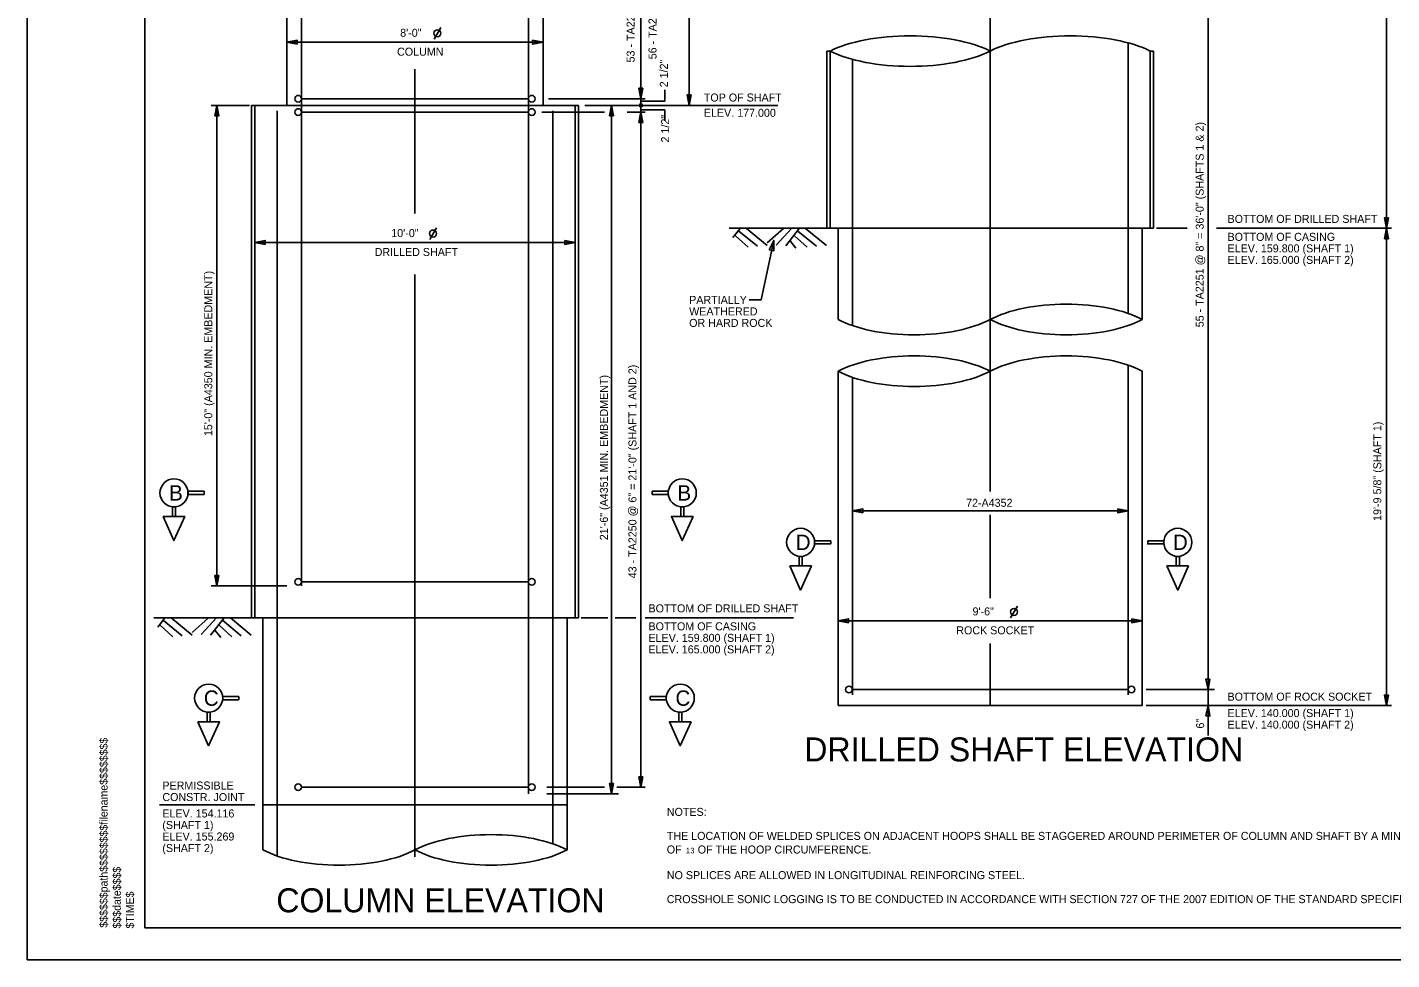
# Model space of a CAD drawing. Extents: x -225.1 to -152.9, y -16.8 to 27.2.
# Drawn here: x -225.08 to -182.47, y -16.78 to 12.34 of the extents above; entities that cross this region are included whole.
import ezdxf

# ---------------------------------------------------------------- set-up
doc = ezdxf.new("R2010")
doc.units = 0
for name, color, linetype in [('BR_AUTO DIMENSION', 7, 'Continuous'), ('BR_BORDER LINES', 7, 'Continuous'), ('BR_CENTER LINES', 7, 'Continuous'), ('BR_CONCRETE', 7, 'Continuous'), ('BR_GRID LINES', 7, 'Continuous'), ('BR_REBAR', 7, 'Continuous'), ('BR_STRUCTURAL STEEL', 7, 'Continuous'), ('BR_TEXT', 7, 'Continuous'), ('Level 31', 7, 'Continuous'), ('RD_SHT_ID', 7, 'Continuous')]:
    doc.layers.add(name, color=color, linetype=linetype)

msp = doc.modelspace()

# ---------------------------------------------------------------- linework, layer by layer
at = {"layer": 'BR_AUTO DIMENSION'}
for p, q in [((-204.41, 23.713), (-204.41, 9.901)), ((-205.915, 23.213), (-205.915, 10.109)), ((-182.63, 22.62), (-182.63, 6.062)), ((-188.204, 22.12), (-188.204, -8.337)), ((-216.97, 11.875), (-208.97, 11.875)), ((-205.169, 10.037), (-205.169, 10.382)), ((-218.137, 9.901), (-219.334, 9.901)), ((-219.156, 9.901), (-219.156, -5.099)), ((-208.796, 10.109), (-205.776, 10.109)), ((-207.661, 9.901), (-201.638, 9.901)), ((-206.836, 9.901), (-206.836, -11.599)), ((-205.915, 10.109), (-205.915, 9.692)), ((-205.169, 10.037), (-205.915, 10.037)), ((-209.012, 9.692), (-207.049, 9.692)), ((-206.342, 9.692), (-205.776, 9.692)), ((-205.169, 9.764), (-205.915, 9.764)), ((-205.915, 9.692), (-205.915, -11.391)), ((-205.169, 9.764), (-205.169, 9.419)), ((-189.813, 6.062), (-188.85, 6.062)), ((-187.938, 6.062), (-182.47, 6.062)), ((-182.63, 6.062), (-182.63, -8.837)), ((-217.97, 5.62), (-207.97, 5.62)), ((-202.163, 3.833), (-201.767, 5.683)), ((-202.537, 3.833), (-202.163, 3.833)), ((-199.311, -2.757), (-196.546, -2.757)), ((-196.546, -2.757), (-190.7, -2.757)), ((-216.972, -5.099), (-219.334, -5.099)), ((-207.777, -6.099), (-206.951, -6.099)), ((-206.72, -6.099), (-206.07, -6.099)), ((-205.786, -6.099), (-201.148, -6.099)), ((-199.756, -6.193), (-190.256, -6.193)), ((-190.138, -8.337), (-188.002, -8.337)), ((-188.204, -8.337), (-188.204, -9.772)), ((-190.138, -8.837), (-182.47, -8.837)), ((-208.847, -11.391), (-207.049, -11.391)), ((-206.665, -11.391), (-205.776, -11.391)), ((-208.847, -11.599), (-206.617, -11.599)), ((-220.947, -11.94), (-217.966, -11.94))]:
    msp.add_line(p, q, dxfattribs=at)
for points in [[(-216.645, 11.812), (-216.97, 11.875), (-216.645, 11.937)], [(-209.295, 11.937), (-208.97, 11.875), (-209.295, 11.812)], [(-205.853, 10.434), (-205.915, 10.109), (-205.978, 10.434)], [(-219.218, 9.576), (-219.156, 9.901), (-219.093, 9.576)], [(-206.899, 9.576), (-206.836, 9.901), (-206.774, 9.576)], [(-204.348, 10.226), (-204.41, 9.901), (-204.473, 10.226)], [(-205.978, 9.367), (-205.915, 9.692), (-205.853, 9.367)], [(-182.568, 6.387), (-182.63, 6.062), (-182.693, 6.387)], [(-182.693, 5.737), (-182.63, 6.062), (-182.568, 5.737)], [(-217.645, 5.557), (-217.97, 5.62), (-217.645, 5.682)], [(-208.295, 5.682), (-207.97, 5.62), (-208.295, 5.557)], [(-201.904, 5.394), (-201.767, 5.683), (-201.764, 5.363)], [(-198.986, -2.819), (-199.311, -2.757), (-198.986, -2.694)], [(-191.025, -2.694), (-190.7, -2.757), (-191.025, -2.819)], [(-219.093, -4.774), (-219.156, -5.099), (-219.218, -4.774)], [(-199.431, -6.256), (-199.756, -6.193), (-199.431, -6.131)], [(-190.581, -6.131), (-190.256, -6.193), (-190.581, -6.256)], [(-188.142, -8.012), (-188.204, -8.337), (-188.267, -8.012)], [(-182.568, -8.512), (-182.63, -8.837), (-182.693, -8.512)], [(-188.267, -9.162), (-188.204, -8.837), (-188.142, -9.162)], [(-205.853, -11.066), (-205.915, -11.391), (-205.978, -11.066)], [(-206.774, -11.274), (-206.836, -11.599), (-206.899, -11.274)]]:
    msp.add_lwpolyline(points, close=True, dxfattribs=at)
msp.add_circle((-205.915, 9.901), 0.0469, dxfattribs=at)
at = {"layer": 'BR_BORDER LINES'}
for q in [(-221.411, 26.224), (-154.078, -15.776)]:
    msp.add_line((-221.411, -15.776), q, dxfattribs=at)
at = {"layer": 'BR_CENTER LINES'}
for p, q in [((-195.006, -2.16), (-195.006, 20.107)), ((-212.97, 6.529), (-212.97, 11.027)), ((-212.97, -13.564), (-212.97, 4.618)), ((-195.006, -5.482), (-195.006, -2.889)), ((-195.006, -8.837), (-195.006, -6.907))]:
    msp.add_line(p, q, dxfattribs=at)
at = {"layer": 'BR_CONCRETE'}
for p, q in [((-216.97, 16.046), (-216.97, 9.901)), ((-208.97, 16.046), (-208.97, 9.901)), ((-200.006, 6.062), (-200.006, 11.596)), ((-190.006, 6.062), (-190.006, 11.596)), ((-217.97, 9.901), (-207.97, 9.901)), ((-217.97, -6.099), (-217.97, 9.901)), ((-207.97, -6.099), (-207.97, 9.901)), ((-200.006, 6.062), (-190.006, 6.062)), ((-199.756, 3.215), (-199.756, 6.062)), ((-190.256, 3.215), (-190.256, 6.062)), ((-199.756, -8.837), (-199.756, 1.6)), ((-190.256, -8.837), (-190.256, 1.6)), ((-217.97, -6.099), (-207.97, -6.099)), ((-217.72, -13.348), (-217.72, -6.099)), ((-208.22, -13.348), (-208.22, -6.099)), ((-199.756, -8.837), (-190.256, -8.837)), ((-208.22, -11.94), (-217.72, -11.94))]:
    msp.add_line(p, q, dxfattribs=at)
for centre, major_axis, ratio, start_param, end_param in [((-197.506, 10.874), (3.13, 0), 0.383333, 0.645812, 2.495781), ((-192.506, 10.874), (3.13, 0), 0.383333, 0.645812, 2.495781), ((-197.506, 12.318), (3.13, 0), 0.383333, 3.787404, 5.637374), ((-192.631, 2.493), (2.974, 0), 0.403509, 0.645812, 2.495781), ((-197.381, 3.937), (2.974, 0), 0.403509, 3.787404, 5.637374), ((-192.631, 3.937), (2.974, 0), 0.403509, 3.787404, 5.637374), ((-197.381, 0.878), (2.974, 0), 0.403509, 0.645812, 2.495781), ((-192.631, 0.878), (2.974, 0), 0.403509, 0.645812, 2.495781), ((-197.381, 2.322), (2.974, 0), 0.403509, 3.787404, 5.637374), ((-210.595, -14.07), (2.974, 0), 0.403509, 0.645812, 2.495781), ((-215.345, -12.625), (2.974, 0), 0.403509, 3.787404, 5.637374), ((-210.595, -12.625), (2.974, 0), 0.403509, 3.787404, 5.637374)]:
    msp.add_ellipse(centre, major_axis=major_axis, ratio=ratio, start_param=start_param, end_param=end_param, dxfattribs=at)
at = {"layer": 'BR_GRID LINES'}
for p, q in [((-203.16, 6.062), (-200.123, 6.062)), ((-202.815, 6.059), (-203.041, 5.771)), ((-202.856, 5.978), (-202.276, 5.501)), ((-202.617, 6.057), (-201.969, 5.523)), ((-201.455, 6.062), (-201.969, 5.606)), ((-201.209, 6.059), (-201.685, 5.541)), ((-200.969, 6.059), (-201.392, 5.52)), ((-201.01, 5.978), (-200.431, 5.501)), ((-200.771, 6.057), (-200.123, 5.523)), ((-202.962, 5.83), (-202.566, 5.469)), ((-201.257, 5.675), (-201.071, 5.447)), ((-201.116, 5.83), (-200.721, 5.469)), ((-221.124, -6.099), (-218.087, -6.099)), ((-220.779, -6.103), (-221.005, -6.39)), ((-220.927, -6.332), (-220.531, -6.692)), ((-220.821, -6.183), (-220.241, -6.661)), ((-220.582, -6.105), (-219.933, -6.639)), ((-219.42, -6.099), (-219.933, -6.556)), ((-219.173, -6.103), (-219.65, -6.621)), ((-218.933, -6.103), (-219.356, -6.641)), ((-219.081, -6.332), (-218.685, -6.692)), ((-218.975, -6.183), (-218.395, -6.661)), ((-218.736, -6.105), (-218.087, -6.639)), ((-219.222, -6.486), (-219.036, -6.714))]:
    msp.add_line(p, q, dxfattribs=at)
at = {"layer": 'BR_REBAR'}
for p, q in [((-209.429, -11.599), (-209.429, 16.396)), ((-216.512, -5.099), (-216.512, 15.696)), ((-190.7, 11.854), (-190.7, 3.406)), ((-199.311, 11.338), (-199.311, 3.024)), ((-216.512, 10.109), (-209.429, 10.109)), ((-217.276, 9.734), (-217.276, -13.538)), ((-216.512, 9.692), (-209.429, 9.692)), ((-208.665, 9.734), (-208.665, -13.157)), ((-190.7, 1.79), (-190.7, -8.504)), ((-199.311, 1.409), (-199.311, -8.504)), ((-216.512, -4.974), (-209.429, -4.974)), ((-199.311, -8.337), (-190.7, -8.337)), ((-216.512, -11.391), (-209.429, -11.391))]:
    msp.add_line(p, q, dxfattribs=at)
at = {"layer": 'BR_STRUCTURAL STEEL'}
for p, q in [((-200.11, 6.062), (-200.11, 11.596)), ((-200.11, 11.596), (-200.006, 11.596)), ((-190.006, 11.596), (-189.902, 11.596)), ((-189.902, 6.062), (-189.902, 11.596)), ((-218.075, -6.099), (-218.075, 9.901)), ((-217.97, 9.901), (-218.075, 9.901)), ((-207.97, 9.901), (-207.866, 9.901)), ((-207.866, -6.099), (-207.866, 9.901)), ((-200.11, 6.062), (-200.006, 6.062)), ((-190.006, 6.062), (-189.902, 6.062)), ((-218.074, -6.099), (-217.97, -6.099)), ((-207.97, -6.099), (-207.866, -6.099))]:
    msp.add_line(p, q, dxfattribs=at)
at = {"layer": 'BR_TEXT'}
for p, q in [((-212.374, 11.97), (-212.164, 12.334)), ((-212.511, 5.716), (-212.301, 6.08)), ((-194.368, -6.098), (-194.158, -5.734))]:
    msp.add_line(p, q, dxfattribs=at)
for points in [[(-219.558, -2.149), (-219.558, -2.249), (-220.059, -2.249), (-220.059, -2.149)], [(-205.56, -2.149), (-205.56, -2.249), (-205.06, -2.249), (-205.06, -2.149)], [(-220.834, -2.937), (-220.496, -3.688), (-220.159, -2.937)], [(-220.446, -2.637), (-220.446, -2.937), (-220.546, -2.937), (-220.546, -2.637)], [(-204.284, -2.937), (-204.622, -3.688), (-204.96, -2.937)], [(-204.672, -2.637), (-204.672, -2.937), (-204.572, -2.937), (-204.572, -2.637)], [(-199.988, -3.693), (-199.988, -3.793), (-200.488, -3.793), (-200.488, -3.693)], [(-190.085, -3.693), (-190.085, -3.793), (-189.585, -3.793), (-189.585, -3.693)], [(-200.876, -4.181), (-200.876, -4.481), (-200.976, -4.481), (-200.976, -4.181)], [(-189.197, -4.181), (-189.197, -4.481), (-189.097, -4.481), (-189.097, -4.181)], [(-201.264, -4.481), (-200.926, -5.232), (-200.588, -4.481)], [(-188.809, -4.481), (-189.147, -5.232), (-189.485, -4.481)], [(-218.475, -8.558), (-218.475, -8.658), (-218.975, -8.658), (-218.975, -8.558)], [(-205.622, -8.558), (-205.622, -8.658), (-205.122, -8.658), (-205.122, -8.558)], [(-219.751, -9.346), (-219.413, -10.097), (-219.076, -9.346)], [(-219.363, -9.046), (-219.363, -9.346), (-219.463, -9.346), (-219.463, -9.046)], [(-204.346, -9.346), (-204.684, -10.097), (-205.022, -9.346)], [(-204.734, -9.046), (-204.734, -9.346), (-204.634, -9.346), (-204.634, -9.046)]]:
    msp.add_lwpolyline(points, close=True, dxfattribs=at)
for centre, radius in [((-212.269, 12.152), 0.11), ((-216.616, 10.109), 0.104), ((-209.324, 10.109), 0.104), ((-216.616, 9.692), 0.104), ((-209.324, 9.692), 0.104), ((-212.406, 5.898), 0.11), ((-220.496, -2.199), 0.438), ((-204.622, -2.199), 0.438), ((-200.926, -3.743), 0.438), ((-189.147, -3.743), 0.438), ((-216.616, -4.974), 0.104), ((-209.324, -4.974), 0.104), ((-194.263, -5.916), 0.11), ((-219.413, -8.608), 0.438), ((-204.684, -8.608), 0.438), ((-199.416, -8.337), 0.104), ((-190.596, -8.337), 0.104), ((-216.616, -11.391), 0.104), ((-209.324, -11.391), 0.104)]:
    msp.add_circle(centre, radius, dxfattribs=at)
at = {"layer": 'Level 31'}
msp.add_lwpolyline([(-225.077, -16.776), (-153.077, -16.776), (-153.077, 27.224), (-225.077, 27.224)], close=True, dxfattribs=at)

# ---------------------------------------------------------------- texts
at = {"layer": 'BR_AUTO DIMENSION'}
for s, p in [('8\'-0"', (-213.432, 12.042)), ('COLUMN', (-213.529, 11.452)), ('10\'-0"', (-213.71, 5.788)), ('DRILLED SHAFT', (-214.228, 5.197)), ('PARTIALLY', (-204.407, 3.703)), ('WEATHERED', (-204.407, 3.343)), ('OR HARD ROCK', (-204.407, 2.983)), ('72-A4352', (-195.759, -2.634)), ('9\'-6"', (-195.558, -6.025)), ('ROCK SOCKET', (-196.065, -6.616))]:
    msp.add_text(s, height=0.25, dxfattribs=at).set_placement(p)
at = {"layer": 'BR_TEXT'}
for s, p in [('53 - TA2250 @ 6" MAX. = 25\'-10 13/16" (COLUMN 1)', (-206.11, 11.241)), ('56 - TA2250 @ 6" MAX. = 27\'-0 11/16" (COLUMN 2)', (-205.427, 11.34)), ('2 1/2"', (-205.073, 10.465)), ('2 1/2"', (-205.033, 8.742)), ('55 - TA2251 @ 8" = 36\'-0" (SHAFTS 1 & 2)', (-188.339, 2.972)), ('15\'-0" (A4350 MIN. EMBEDMENT)', (-219.3, -0.427)), ('43 - TA2250 @ 6" = 21\'-0" (SHAFT 1 AND 2)', (-206.053, -4.867)), ('21\'-6" (A4351 MIN. EMBEDMENT)', (-206.945, -3.677)), ('19\'-9 5/8" (SHAFT 1)', (-182.792, -3.075)), ('6"', (-188.324, -9.559))]:
    msp.add_text(s, height=0.25, rotation=90, dxfattribs=at).set_placement(p)
for s, height, p in [('TOP OF SHAFT', 0.25, (-203.949, 10.021)), ('ELEV. 177.000', 0.25, (-203.949, 9.544)), ('BOTTOM OF DRILLED SHAFT', 0.25, (-187.594, 6.231)), ('BOTTOM OF CASING', 0.25, (-187.594, 5.671)), ('ELEV. 159.800 (SHAFT 1)', 0.25, (-187.594, 5.311)), ('ELEV. 165.000 (SHAFT 2)', 0.25, (-187.594, 4.951)), ('B', 0.48, (-220.648, -2.439)), ('B', 0.48, (-204.773, -2.439)), ('D', 0.48, (-201.079, -3.983)), ('D', 0.48, (-189.3, -3.983)), ('BOTTOM OF DRILLED SHAFT', 0.25, (-205.678, -5.93)), ('BOTTOM OF CASING', 0.25, (-205.678, -6.491)), ('ELEV. 159.800 (SHAFT 1)', 0.25, (-205.678, -6.851)), ('ELEV. 165.000 (SHAFT 2)', 0.25, (-205.678, -7.211)), ('C', 0.48, (-219.564, -8.848)), ('C', 0.48, (-204.835, -8.848)), ('BOTTOM OF ROCK SOCKET', 0.25, (-187.594, -8.687)), ('ELEV. 140.000 (SHAFT 1)', 0.25, (-187.594, -9.2)), ('ELEV. 140.000 (SHAFT 2)', 0.25, (-187.594, -9.561)), ('DRILLED SHAFT ELEVATION', 0.75, (-200.814, -10.585)), ('PERMISSIBLE', 0.25, (-220.859, -11.462)), ('CONSTR. JOINT', 0.25, (-220.859, -11.822)), ('ELEV. 154.116', 0.25, (-220.859, -12.334)), ('NOTES:', 0.25, (-205.105, -12.285)), ('(SHAFT 1)', 0.25, (-220.859, -12.694)), ('THE LOCATION OF WELDED SPLICES ON ADJACENT HOOPS SHALL BE STAGGERED AROUND PERIMETER OF COLUMN AND SHAFT BY A MINIMUM', 0.249999, (-205.105, -13.035)), ('(SHAFT 2)', 0.25, (-220.859, -13.415)), ('ELEV. 155.269', 0.25, (-220.859, -13.054)), ('OF ', 0.25, (-205.105, -13.46)), (' OF THE HOOP CIRCUMFERENCE.', 0.25, (-204.232, -13.46)), ('1', 0.175, (-204.51, -13.457)), ('3', 0.175, (-204.371, -13.457)), ('NO SPLICES ARE ALLOWED IN LONGITUDINAL REINFORCING STEEL.', 0.25, (-205.105, -14.26)), ('COLUMN ELEVATION', 0.75, (-217.302, -15.296)), ('CROSSHOLE SONIC LOGGING IS TO BE CONDUCTED IN ACCORDANCE WITH SECTION 727 OF THE 2007 EDITION OF THE STANDARD SPECIFICATIONS.', 0.249999, (-205.105, -15.01))]:
    msp.add_text(s, height=height, dxfattribs=at).set_placement(p)
at = {"layer": 'RD_SHT_ID'}
for s, height, p in [('$$$$$$path$$$$$$$$filename$$$$$$$$', 0.24694, (-222.57, -15.776)), ('$$$date$$$$', 0.24694, (-222.158, -15.802)), ('$TIME$', 0.2469, (-221.749, -15.802))]:
    msp.add_text(s, height=height, rotation=90, dxfattribs=at).set_placement(p)

doc.saveas('drawing.dxf')
